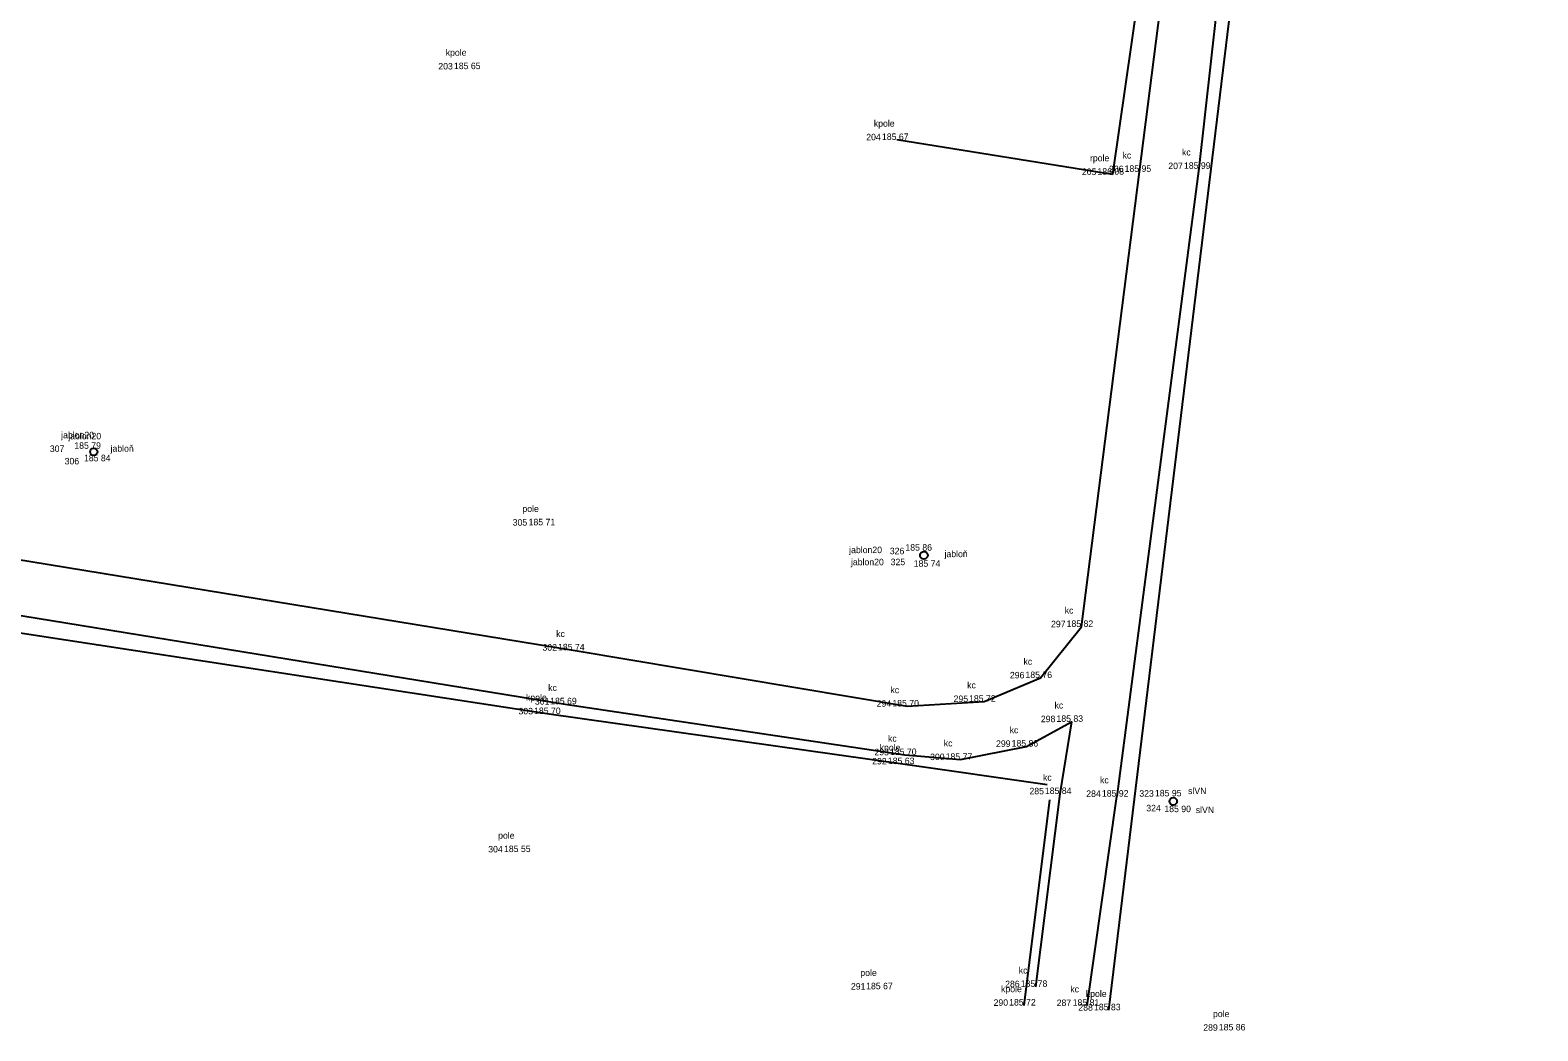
# Model space of a CAD drawing. Extents: x -598527 to -598215, y -1172822 to -1172560.
# Drawn here: x -598316.7 to -598247.1, y -1172725.4 to -1172679.2 of the extents above; entities that cross this region are included whole.
import ezdxf

# ---------------------------------------------------------------- set-up
doc = ezdxf.new("R2010")
doc.units = 0
for name, color, linetype in [('Body', 7, 'Continuous'), ('Body čísla', 7, 'Continuous'), ('Kody', 7, 'Continuous'), ('Kraj pole', 7, 'Continuous'), ('PATTERN_CLASS', 7, 'Continuous'), ('Ploty', 7, 'Continuous'), ('Stromy', 7, 'Continuous'), ('Výšky', 7, 'Continuous')]:
    doc.layers.add(name, color=color, linetype=linetype)

msp = doc.modelspace()

# ---------------------------------------------------------------- linework, layer by layer
at = {"layer": 'Body'}
for p, q in [((-598296.44, -1172681.01), (-598296.44, -1172681.01)), ((-598276.69, -1172684.28), (-598276.69, -1172684.28)), ((-598266.75, -1172685.88), (-598266.75, -1172685.88)), ((-598265.5, -1172685.75), (-598265.5, -1172685.75)), ((-598262.76, -1172685.61), (-598262.76, -1172685.61)), ((-598313.91, -1172698.66), (-598313.91, -1172698.66)), ((-598313.58, -1172698.71), (-598313.58, -1172698.71)), ((-598293.01, -1172702.06), (-598293.01, -1172702.06)), ((-598275.61, -1172703.38), (-598275.61, -1172703.38)), ((-598275.28, -1172703.52), (-598275.28, -1172703.52)), ((-598268.17, -1172706.75), (-598268.17, -1172706.75)), ((-598291.63, -1172707.83), (-598291.63, -1172707.83)), ((-598270.07, -1172709.11), (-598270.07, -1172709.11)), ((-598292, -1172710.32), (-598292, -1172710.32)), ((-598272.67, -1172710.2), (-598272.67, -1172710.2)), ((-598292.74, -1172710.77), (-598292.74, -1172710.77)), ((-598276.21, -1172710.42), (-598276.21, -1172710.42)), ((-598268.64, -1172711.13), (-598268.64, -1172711.13)), ((-598270.71, -1172712.27), (-598270.71, -1172712.27)), ((-598276.42, -1172713.08), (-598276.42, -1172713.08)), ((-598276.32, -1172712.66), (-598276.32, -1172712.66)), ((-598273.75, -1172712.88), (-598273.75, -1172712.88)), ((-598269.17, -1172714.46), (-598269.17, -1172714.46)), ((-598266.54, -1172714.58), (-598266.54, -1172714.58)), ((-598264.1, -1172714.74), (-598264.1, -1172714.74)), ((-598263.77, -1172714.82), (-598263.77, -1172714.82)), ((-598294.13, -1172717.14), (-598294.13, -1172717.14)), ((-598277.42, -1172723.47), (-598277.42, -1172723.47)), ((-598270.29, -1172723.36), (-598270.29, -1172723.36)), ((-598270.82, -1172724.22), (-598270.82, -1172724.22)), ((-598267.91, -1172724.23), (-598267.91, -1172724.23)), ((-598266.91, -1172724.44), (-598266.91, -1172724.44)), ((-598261.15, -1172725.37), (-598261.15, -1172725.37))]:
    msp.add_line(p, q, dxfattribs=at)
at = {"layer": 'Kraj pole'}
for p, q in [((-598263.23, -1172661.6), (-598266.75, -1172685.88)), ((-598266.91, -1172724.44), (-598260.78, -1172673.98)), ((-598266.75, -1172685.88), (-598276.69, -1172684.28)), ((-598276.42, -1172713.08), (-598269.758, -1172714.023)), ((-598270.82, -1172724.22), (-598269.627, -1172714.729))]:
    msp.add_line(p, q, dxfattribs=at)
at = {"layer": 'PATTERN_CLASS'}
for p, q in [((-598262.76, -1172685.61), (-598266.54, -1172714.58)), ((-598269.17, -1172714.46), (-598270.29, -1172723.36)), ((-598267.91, -1172724.23), (-598266.54, -1172714.58))]:
    msp.add_line(p, q, dxfattribs=at)
for points in [[(-598268.17, -1172706.75), (-598265.5, -1172685.75), (-598263.77, -1172672.23), (-598261.78, -1172661.56), (-598259.91, -1172647.93), (-598258.56, -1172636.35), (-598257.55, -1172628.24), (-598255.85, -1172620.63), (-598252.54, -1172611.06), (-598250.18, -1172605.62), (-598248.3, -1172599.38), (-598247.28, -1172594.11), (-598247.12, -1172592.75), (-598247.32, -1172591.46), (-598247.682, -1172590.57), (-598248.25, -1172589.72), (-598249.298, -1172588.918), (-598249.871, -1172588.59), (-598250.6, -1172588.3), (-598252.47, -1172587.89)], [(-598253.34, -1172621.16), (-598254.92, -1172628.91), (-598255.77, -1172636.64), (-598257.28, -1172648.19), (-598259.24, -1172661.8), (-598261.36, -1172673.07), (-598262.76, -1172685.61)], [(-598492.58, -1172680.02), (-598468.55, -1172682.91), (-598441.63, -1172686.62), (-598421.91, -1172689.41), (-598395.91, -1172693.05), (-598382.12, -1172695.14), (-598364.75, -1172697.57), (-598348.85, -1172699.43), (-598326.25, -1172702.17), (-598291.63, -1172707.83), (-598276.21, -1172710.42), (-598272.67, -1172710.2), (-598270.07, -1172709.11), (-598268.17, -1172706.75)], [(-598504.27, -1172686.48), (-598502.86, -1172683.29), (-598501.21, -1172681.85), (-598498.91, -1172681.7), (-598493.15, -1172682.35), (-598468.61, -1172685.05), (-598441.9, -1172688.98), (-598422.43, -1172691.66), (-598396.42, -1172695.27), (-598382.3, -1172697.44), (-598365.39, -1172699.67), (-598349.07, -1172701.68), (-598326.56, -1172704.69), (-598292, -1172710.32), (-598276.32, -1172712.66), (-598273.75, -1172712.88), (-598270.71, -1172712.27), (-598268.64, -1172711.13), (-598269.17, -1172714.46)]]:
    msp.add_lwpolyline(points, dxfattribs=at)
msp.add_circle((-598263.941, -1172714.805), 0.172, dxfattribs=at)
at = {"layer": 'Ploty'}
for p, q in [((-598326.85, -1172705.54), (-598292.74, -1172710.77)), ((-598292.74, -1172710.77), (-598276.42, -1172713.08))]:
    msp.add_line(p, q, dxfattribs=at)
at = {"layer": 'Stromy'}
for centre, radius in [((-598313.744, -1172698.678), 0.167), ((-598275.445, -1172703.45), 0.179)]:
    msp.add_circle(centre, radius, dxfattribs=at)

# ---------------------------------------------------------------- texts
at = {"layer": 'Body čísla'}
for s, p in [('203', (-598297.847, -1172681.033)), ('204', (-598278.104, -1172684.303)), ('205', (-598268.155, -1172685.903)), ('206', (-598266.907, -1172685.773)), ('207', (-598264.168, -1172685.633)), ('307', (-598315.769, -1172698.683)), ('306', (-598315.086, -1172699.258)), ('305', (-598294.415, -1172702.083)), ('326', (-598277.017, -1172703.403)), ('325', (-598276.978, -1172703.909)), ('297', (-598269.578, -1172706.773)), ('302', (-598293.041, -1172707.853)), ('296', (-598271.477, -1172709.133)), ('301', (-598293.391, -1172710.343)), ('294', (-598277.624, -1172710.443)), ('295', (-598274.075, -1172710.223)), ('303', (-598294.147, -1172710.793)), ('298', (-598270.048, -1172711.153)), ('293', (-598277.727, -1172712.683)), ('299', (-598272.116, -1172712.293)), ('292', (-598277.831, -1172713.103)), ('300', (-598275.16, -1172712.903)), ('285', (-598270.575, -1172714.483)), ('284', (-598267.954, -1172714.603)), ('323', (-598265.507, -1172714.592)), ('324', (-598265.184, -1172715.268)), ('304', (-598295.544, -1172717.163)), ('291', (-598278.811, -1172723.493)), ('286', (-598271.697, -1172723.383)), ('290', (-598272.23, -1172724.243)), ('287', (-598269.318, -1172724.253)), ('288', (-598268.318, -1172724.463)), ('289', (-598262.556, -1172725.393))]:
    msp.add_text(s, height=0.3, dxfattribs=at).set_placement(p)
at = {"layer": 'Kody'}
for s, p in [('kpole', (-598297.504, -1172680.403)), ('kpole', (-598277.754, -1172683.673)), ('rpole', (-598267.783, -1172685.273)), ('kc', (-598266.278, -1172685.143)), ('kc', (-598263.538, -1172685.003)), ('jablon20', (-598315.247, -1172698.053)), ('jablon20', (-598314.917, -1172698.103)), ('pole', (-598293.967, -1172701.453)), ('jablon20', (-598278.893, -1172703.353)), ('jablon20', (-598278.81, -1172703.912)), ('kc', (-598268.948, -1172706.143)), ('kc', (-598292.408, -1172707.223)), ('kc', (-598270.848, -1172708.503)), ('kc', (-598292.778, -1172709.713)), ('kc', (-598276.988, -1172709.813)), ('kc', (-598273.448, -1172709.593)), ('kpole', (-598293.804, -1172710.163)), ('kc', (-598269.418, -1172710.523)), ('kc', (-598271.488, -1172711.663)), ('kpole', (-598277.484, -1172712.473)), ('kc', (-598277.098, -1172712.053)), ('kc', (-598274.528, -1172712.273)), ('kc', (-598269.948, -1172713.853)), ('kc', (-598267.318, -1172713.973)), ('slVN', (-598263.257, -1172714.472)), ('slVN', (-598262.903, -1172715.348)), ('pole', (-598295.087, -1172716.533)), ('pole', (-598278.377, -1172722.863)), ('kc', (-598271.068, -1172722.753)), ('kpole', (-598271.884, -1172723.613)), ('kc', (-598268.688, -1172723.623)), ('kpole', (-598267.974, -1172723.833)), ('pole', (-598262.107, -1172724.763))]:
    msp.add_text(s, height=0.3, dxfattribs=at).set_placement(p)
at = {"layer": 'Stromy'}
for p in [(-598312.969, -1172698.672), (-598274.494, -1172703.538)]:
    msp.add_text('jabloň', height=0.3, dxfattribs=at).set_placement(p)
at = {"layer": 'Výšky'}
for s, p in [('185 65', (-598297.126, -1172681.018)), ('185 67', (-598277.379, -1172684.288)), ('186 08', (-598267.438, -1172685.888)), ('185 95', (-598266.186, -1172685.758)), ('185 99', (-598263.447, -1172685.618)), ('185 79', (-598314.639, -1172698.538)), ('185 84', (-598314.193, -1172699.113)), ('185 71', (-598293.681, -1172702.068)), ('185 86', (-598276.298, -1172703.239)), ('185 74', (-598275.913, -1172703.981)), ('185 82', (-598268.861, -1172706.758)), ('185 74', (-598292.324, -1172707.838)), ('185 76', (-598270.758, -1172709.118)), ('185 69', (-598292.687, -1172710.328)), ('185 70', (-598276.9, -1172710.428)), ('185 72', (-598273.361, -1172710.208)), ('185 70', (-598293.43, -1172710.778)), ('185 83', (-598269.327, -1172711.138)), ('185 70', (-598277.01, -1172712.668)), ('185 86', (-598271.398, -1172712.278)), ('185 63', (-598277.107, -1172713.088)), ('185 77', (-598274.439, -1172712.888)), ('185 84', (-598269.864, -1172714.468)), ('185 92', (-598267.231, -1172714.588)), ('185 95', (-598264.786, -1172714.577)), ('185 90', (-598264.351, -1172715.305)), ('185 55', (-598294.816, -1172717.148)), ('185 67', (-598278.109, -1172723.478)), ('185 78', (-598270.978, -1172723.368)), ('185 72', (-598271.511, -1172724.228)), ('185 81', (-598268.581, -1172724.238)), ('185 83', (-598267.597, -1172724.448)), ('185 86', (-598261.838, -1172725.378))]:
    msp.add_text(s, height=0.3, dxfattribs=at).set_placement(p)

doc.saveas('drawing.dxf')
